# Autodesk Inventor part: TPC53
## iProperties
Shininess: 64.0
Length Units: 11272
Angle Units: 11279
Time Units: 11290
Mass Units: 11286
Length Display Precision: 3
Angle Display Precision: 2
Compacted: True
Part Number: TPC53
Document SubType Name: Modeling
Created: 2004-08
Designer: Lori
Manufacturer: Standard
Standards Organization: Custom
Density: 0.0
Volumn: 0.0
Area: 0.0
PropertySet Name: Model Information
Control State: 0
Master: False
Checked Out: False
Author: Lori
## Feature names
1. Base1
